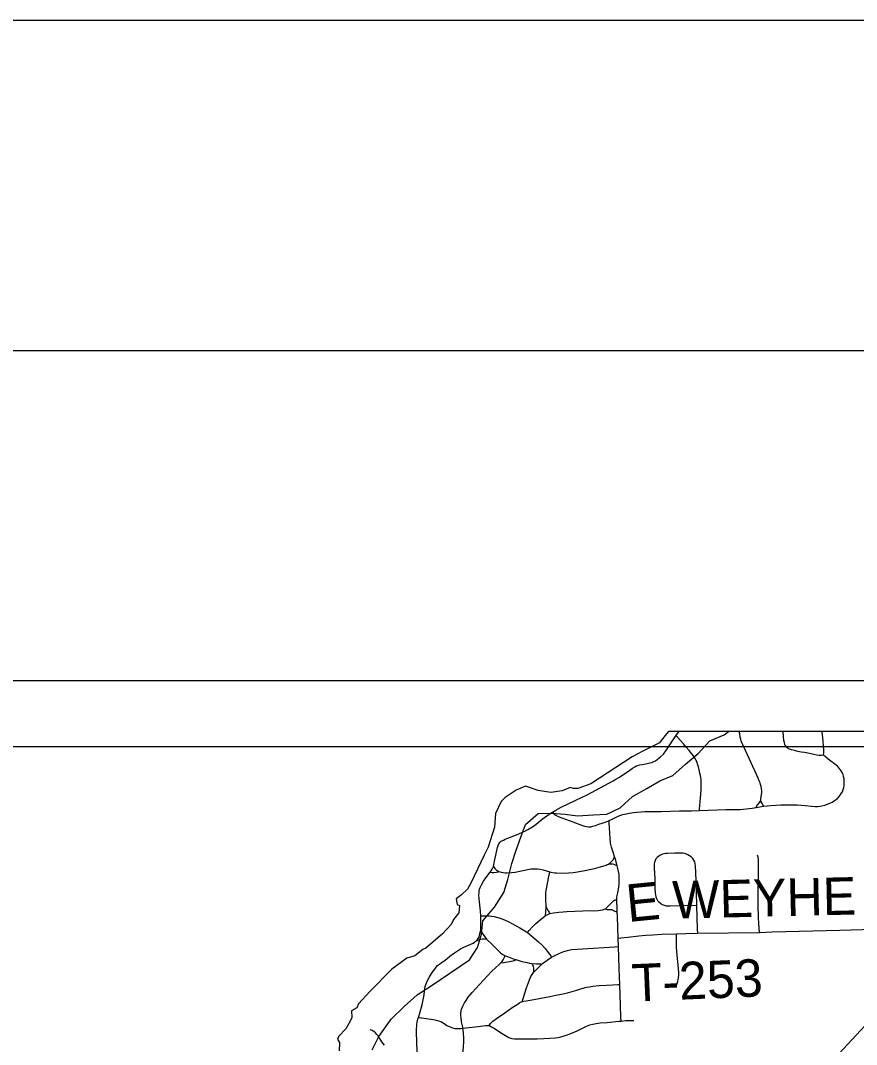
# Model space of a CAD drawing. Extents: x 63.4 to 97.4, y 0.4 to 22.4.
# Drawn here: x 67.147 to 68.414, y 20.868 to 22.42 of the extents above; entities that cross this region are included whole.
import ezdxf

# ---------------------------------------------------------------- set-up
doc = ezdxf.new("R2010")
doc.units = 0
for name, color, linetype in [('GM_X_County_Road', 7, 'Continuous'), ('GM_X_Major_Lake', 7, 'Continuous'), ('GM_X_Township_Road', 7, 'Continuous'), ('GM_X_Township_Road_Text', 7, 'Continuous'), ('SH_Border', 7, 'Continuous'), ('SH_Cut_Line', 7, 'Continuous'), ('SH_Data', 7, 'Continuous')]:
    doc.layers.add(name, color=color, linetype=linetype)

msp = doc.modelspace()

# ---------------------------------------------------------------- linework, layer by layer
at = {"layer": 'GM_X_County_Road'}
for points in [[(69.014, 21.3427), (68.1287, 21.3427), (68.1259, 21.3388), (68.1162, 21.3269), (68.1151, 21.3254), (68.0888, 21.312), (68.0738, 21.3043), (68.0114, 21.2632), (67.9915, 21.2561), (67.9849, 21.2559), (67.9798, 21.2576), (67.9678, 21.2528), (67.9506, 21.2499), (67.9313, 21.2531), (67.9121, 21.2599), (67.8979, 21.2536), (67.8814, 21.2424), (67.8754, 21.2367), (67.8665, 21.2183), (67.8653, 21.1977), (67.8557, 21.1674), (67.8494, 21.155), (67.8294, 21.1127), (67.8243, 21.1037), (67.8152, 21.095), (67.8072, 21.0889), (67.8087, 21.0803), (67.8123, 21.0787), (67.8113, 21.0677), (67.8029, 21.0578), (67.7996, 21.0501), (67.7865, 21.036), (67.761, 21.0143), (67.7564, 21.0123), (67.7444, 21.0026), (67.7325, 20.9991), (67.7094, 20.9826), (67.677, 20.9492), (67.6592, 20.9301), (67.6566, 20.924), (67.6487, 20.9191), (67.6488, 20.909), (67.6466, 20.9039), (67.6421, 20.8957), (67.6401, 20.8918), (67.6295, 20.8811), (67.6273, 20.8763), (67.6304, 20.8715), (67.6298, 20.8585)], [(68.3449, 20.8), (68.3483, 20.8062), (68.3529, 20.8134), (68.3582, 20.8212), (68.3639, 20.8286), (68.372, 20.8381), (68.3868, 20.8541), (68.4335, 20.9041), (68.4571, 20.9289), (68.5232, 20.999), (68.54, 21.0174), (68.546, 21.0244), (68.5516, 21.0318), (68.5584, 21.0421), (68.5614, 21.0469)]]:
    msp.add_lwpolyline(points, dxfattribs=at)
at = {"layer": 'GM_X_Major_Lake'}
for points in [[(67.9121, 21.2016), (67.9315, 21.2183), (67.9516, 21.2187), (67.9721, 21.2172), (67.991, 21.2149), (68.015, 21.216), (68.0354, 21.2172), (68.0556, 21.2271), (68.0745, 21.2438), (68.0958, 21.2559), (68.1159, 21.2677), (68.1356, 21.2757), (68.1546, 21.2932), (68.1736, 21.3091), (68.1914, 21.3285), (68.2134, 21.3376), (68.2196, 21.3427)], [(67.9121, 21.2016), (67.9315, 21.2183), (67.9516, 21.2187), (67.9721, 21.2172), (67.991, 21.2149), (68.015, 21.216), (68.0354, 21.2172), (68.0556, 21.2271), (68.0745, 21.2438), (68.0958, 21.2559), (68.1159, 21.2677), (68.1356, 21.2757), (68.1546, 21.2932), (68.1736, 21.3091), (68.1914, 21.3285), (68.2134, 21.3376), (68.2196, 21.3427)], [(67.6799, 20.8604), (67.6901, 20.8805), (67.7087, 20.9068), (67.7281, 20.9261), (67.7482, 20.9436), (67.7694, 20.9573), (67.8271, 20.9964), (67.8393, 21.0154), (67.8453, 21.0356), (67.8476, 21.0557), (67.8651, 21.0766), (67.8791, 21.0986), (67.8852, 21.1184), (67.8916, 21.1423), (67.8981, 21.1625), (67.9053, 21.1826), (67.9121, 21.2016)]]:
    msp.add_lwpolyline(points, dxfattribs=at)
at = {"layer": 'GM_X_Township_Road'}
for p, q in [((68.2619, 21.2275), (68.2735, 21.2295)), ((68.1731, 21.037), (68.2669, 21.0382)), ((68.0531, 21.0168), (68.0527, 21.0293))]:
    msp.add_line(p, q, dxfattribs=at)
for points in [[(67.9533, 21.2205), (67.9582, 21.2235), (67.9662, 21.2278), (67.9886, 21.2385), (68.0054, 21.2466), (68.0448, 21.2676), (68.0492, 21.2701), (68.0547, 21.2734), (68.0613, 21.2778), (68.068, 21.2824), (68.0743, 21.2869), (68.0778, 21.2891), (68.0798, 21.2903), (68.0822, 21.2912), (68.0851, 21.2919), (68.0889, 21.2926), (68.0947, 21.2933), (68.1008, 21.2948), (68.1037, 21.2957), (68.1066, 21.2969), (68.1093, 21.2983), (68.1119, 21.3), (68.1144, 21.3019), (68.1168, 21.3039), (68.1212, 21.3083), (68.125, 21.3131), (68.1301, 21.3209), (68.1401, 21.3361)], [(68.1401, 21.3361), (68.142, 21.3391), (68.145, 21.3427)], [(68.1756, 21.2226), (68.1759, 21.2261), (68.1761, 21.2295), (68.177, 21.2366), (68.1778, 21.2473), (68.1782, 21.2555), (68.1784, 21.2613), (68.1784, 21.2659), (68.1781, 21.2696), (68.1772, 21.2757), (68.1764, 21.2795), (68.1746, 21.2869), (68.1738, 21.2903), (68.173, 21.293), (68.1721, 21.2958), (68.1708, 21.2986), (68.1692, 21.3015), (68.1669, 21.3055), (68.1639, 21.3092), (68.1602, 21.3137), (68.1558, 21.319), (68.1518, 21.3237), (68.1418, 21.3343), (68.1401, 21.3361)], [(68.2685, 21.2385), (68.2688, 21.2407), (68.2695, 21.2441), (68.2703, 21.2495), (68.2703, 21.2526), (68.27, 21.2558), (68.2692, 21.2591), (68.2683, 21.2623), (68.2675, 21.2647), (68.2664, 21.2676), (68.2649, 21.2719), (68.2599, 21.283), (68.2453, 21.3138), (68.2414, 21.3225), (68.2394, 21.327), (68.2388, 21.3285), (68.2384, 21.3302), (68.2376, 21.3338), (68.2368, 21.3388), (68.2359, 21.3427)], [(68.3638, 21.3067), (68.3604, 21.3062), (68.3573, 21.3062), (68.3536, 21.3068), (68.3491, 21.3075), (68.3424, 21.309), (68.3349, 21.3105), (68.3298, 21.3113), (68.3249, 21.3124), (68.3196, 21.3135), (68.3153, 21.3146), (68.312, 21.3156), (68.3103, 21.3165), (68.3087, 21.3178), (68.3078, 21.3186), (68.3064, 21.3202), (68.3058, 21.3213), (68.3052, 21.323), (68.3044, 21.3257), (68.3037, 21.329), (68.303, 21.3347), (68.3024, 21.3427)], [(68.3638, 21.3067), (68.3642, 21.3107), (68.3641, 21.3141), (68.3625, 21.3336), (68.3615, 21.3412), (68.3614, 21.3427)], [(68.2735, 21.2295), (68.2834, 21.2306), (68.2989, 21.2315), (68.3112, 21.2315), (68.3238, 21.2312), (68.3359, 21.2303), (68.3454, 21.2295), (68.3512, 21.229), (68.3545, 21.2291), (68.358, 21.2294), (68.3613, 21.2298), (68.3656, 21.231), (68.3721, 21.2333), (68.3767, 21.2356), (68.3803, 21.2378), (68.3833, 21.2398), (68.3854, 21.2417), (68.3874, 21.2441), (68.3889, 21.2461), (68.3907, 21.2486), (68.3924, 21.2513), (68.3937, 21.2544), (68.3945, 21.2579), (68.3948, 21.2608), (68.395, 21.2641), (68.3949, 21.2671), (68.3948, 21.2707), (68.3942, 21.2745), (68.3934, 21.2775), (68.3922, 21.2802), (68.3903, 21.283), (68.3889, 21.2847), (68.3872, 21.287), (68.3852, 21.2893), (68.3806, 21.2933), (68.375, 21.2975), (68.3708, 21.3008), (68.3638, 21.3067)], [(68.1756, 21.2226), (68.2158, 21.2241), (68.2373, 21.2244), (68.2466, 21.2251), (68.2558, 21.2265), (68.2619, 21.2275)], [(68.2619, 21.2275), (68.2628, 21.2298), (68.2642, 21.2319), (68.2652, 21.2331), (68.2665, 21.2349), (68.2676, 21.2367), (68.2685, 21.2385)], [(68.2735, 21.2295), (68.2718, 21.2316), (68.2708, 21.2332), (68.2694, 21.2361), (68.2685, 21.2385)], [(67.8636, 21.1382), (67.8653, 21.1462), (67.8697, 21.1667), (67.8706, 21.1696), (67.8718, 21.1722), (67.8734, 21.1742), (67.8755, 21.1762), (67.8786, 21.1779), (67.8815, 21.1792), (67.8841, 21.1803), (67.8985, 21.1859), (67.9078, 21.1898), (67.9113, 21.1915), (67.9157, 21.1938), (67.9215, 21.1974), (67.9242, 21.1993), (67.9284, 21.2023), (67.9373, 21.2095), (67.9444, 21.2147), (67.9511, 21.2191), (67.9533, 21.2205)], [(67.9533, 21.2205), (67.9557, 21.2174), (67.9581, 21.2155), (67.9614, 21.2139), (67.9838, 21.2054), (67.9985, 21.2), (68.0017, 21.1989), (68.0046, 21.1984), (68.0076, 21.1981), (68.0109, 21.1983), (68.0142, 21.1989), (68.0183, 21.2002), (68.0232, 21.2019), (68.0282, 21.2037), (68.0342, 21.2058), (68.0389, 21.2075)], [(68.0389, 21.2075), (68.0426, 21.2094), (68.0453, 21.2108), (68.0483, 21.2124), (68.0514, 21.2137), (68.0549, 21.2151), (68.0595, 21.2166), (68.0647, 21.218), (68.0697, 21.219), (68.0756, 21.2198), (68.093, 21.2211), (68.1053, 21.2215), (68.1176, 21.2215), (68.1455, 21.2221), (68.1638, 21.2222), (68.1756, 21.2226)], [(68.0472, 21.1527), (68.0449, 21.1598), (68.0425, 21.1673), (68.0411, 21.1735), (68.0403, 21.1807), (68.0398, 21.1882), (68.0393, 21.1971), (68.0389, 21.2034), (68.0389, 21.2075)], [(68.0378, 21.1416), (68.0406, 21.1434), (68.0425, 21.1453), (68.0449, 21.148), (68.0461, 21.1502), (68.0472, 21.1527)], [(68.0509, 21.1389), (68.0503, 21.1411), (68.0478, 21.1507), (68.0472, 21.1527)], [(68.1718, 21.0794), (68.1706, 21.1172), (68.1698, 21.1389), (68.1694, 21.142), (68.1686, 21.145), (68.1673, 21.1477), (68.1655, 21.1502), (68.1633, 21.1524), (68.1608, 21.1543), (68.1581, 21.1558), (68.1552, 21.157), (68.1531, 21.1577), (68.1513, 21.1581), (68.1492, 21.1583), (68.1462, 21.1584), (68.1384, 21.1582), (68.1275, 21.1578), (68.1246, 21.1576), (68.1221, 21.1573), (68.1199, 21.1566), (68.1179, 21.1559), (68.1156, 21.1546), (68.1137, 21.1533), (68.1116, 21.1514), (68.1098, 21.1494), (68.1086, 21.1473), (68.1076, 21.1447), (68.1071, 21.1417), (68.1069, 21.1391), (68.107, 21.1355), (68.1079, 21.12), (68.1083, 21.1045), (68.1086, 21.0983), (68.109, 21.0953), (68.1097, 21.0922), (68.1108, 21.0893), (68.1124, 21.0866), (68.1143, 21.0842), (68.1166, 21.0822), (68.1192, 21.0805), (68.1221, 21.0793), (68.1251, 21.0786), (68.1282, 21.0783), (68.1313, 21.0783), (68.1718, 21.0794)], [(68.2669, 21.0382), (68.2658, 21.0517), (68.2653, 21.0609), (68.2646, 21.0795), (68.2645, 21.0888), (68.2646, 21.107), (68.2653, 21.1303), (68.2652, 21.1437), (68.265, 21.1485), (68.2646, 21.1519), (68.2637, 21.1552)], [(67.8586, 21.1294), (67.86, 21.1314), (67.8616, 21.1339), (67.8628, 21.1362), (67.8636, 21.1382)], [(67.8636, 21.1382), (67.8645, 21.1364), (67.8655, 21.1349), (67.8665, 21.1338), (67.8673, 21.1332), (67.8682, 21.1325), (67.8693, 21.1317), (67.8718, 21.1305)], [(67.8718, 21.1305), (67.8752, 21.1294), (67.8785, 21.129), (67.8814, 21.1285), (67.8845, 21.1282), (67.8908, 21.1287), (67.8967, 21.1294), (67.9178, 21.1341), (67.9208, 21.1345), (67.9238, 21.1346), (67.9301, 21.1344), (67.9342, 21.1338), (67.939, 21.133), (67.9489, 21.13)], [(67.9489, 21.13), (67.9504, 21.1296), (67.9563, 21.1285), (67.9593, 21.1283), (67.9683, 21.128), (67.9775, 21.1283), (67.9849, 21.1291), (67.9996, 21.1314), (68.0165, 21.1349), (68.0238, 21.1368), (68.0292, 21.1385), (68.0344, 21.1402), (68.0361, 21.1409), (68.0378, 21.1416)], [(68.0378, 21.1416), (68.0415, 21.142), (68.0444, 21.1419), (68.0472, 21.1411), (68.0492, 21.1401), (68.0509, 21.1389)], [(68.0505, 21.0876), (68.0506, 21.0908), (68.051, 21.0942), (68.0519, 21.0979), (68.0531, 21.1038), (68.0542, 21.1109), (68.0543, 21.1159), (68.0543, 21.1199), (68.054, 21.1253), (68.0535, 21.1286), (68.0525, 21.1329), (68.0509, 21.1389)], [(67.8443, 21.0633), (67.8438, 21.0705), (67.8419, 21.0891), (67.8416, 21.0952), (67.8417, 21.0983), (67.842, 21.1012), (67.8426, 21.1037), (67.8434, 21.1061), (67.8456, 21.1103), (67.8486, 21.1157), (67.8521, 21.1208), (67.8586, 21.1294)], [(67.8586, 21.1294), (67.8612, 21.1289), (67.8647, 21.129), (67.8681, 21.1294), (67.8702, 21.1297), (67.8711, 21.13), (67.8718, 21.1305)], [(67.9434, 21.0771), (67.9434, 21.0779), (67.9428, 21.0869), (67.9428, 21.0911), (67.9429, 21.0959), (67.943, 21.0988), (67.9434, 21.1017), (67.9477, 21.1229), (67.9485, 21.1275), (67.9489, 21.13)], [(68.0328, 21.0739), (68.0343, 21.0748), (68.0366, 21.0768), (68.0396, 21.08), (68.0454, 21.0858), (68.0465, 21.0867), (68.0481, 21.0873), (68.0505, 21.0876)], [(68.0511, 21.0698), (68.0509, 21.073), (68.0505, 21.0876)], [(67.9423, 21.0639), (67.9427, 21.065), (67.9432, 21.0686), (67.9434, 21.0771)], [(67.9434, 21.0771), (67.9446, 21.0741), (67.9461, 21.0714), (67.9478, 21.0686), (67.9487, 21.0675), (67.9492, 21.0666)], [(67.9492, 21.0666), (67.9547, 21.0678), (67.9626, 21.0688), (67.9693, 21.0692), (67.9747, 21.0696), (67.9869, 21.0704), (67.999, 21.0709), (68.0109, 21.0712), (68.0156, 21.071), (68.0224, 21.0713), (68.026, 21.0719), (68.0289, 21.0725), (68.0317, 21.0733), (68.0328, 21.0739)], [(68.0328, 21.0739), (68.0355, 21.073), (68.0385, 21.0729), (68.0411, 21.0728), (68.0426, 21.0727), (68.0439, 21.0724), (68.0456, 21.0715), (68.0477, 21.0704), (68.0488, 21.0699), (68.0499, 21.0698), (68.0511, 21.0698)], [(68.0527, 21.0293), (68.0515, 21.0622), (68.0511, 21.0698)], [(68.1731, 21.037), (68.173, 21.0426), (68.1718, 21.0794)], [(67.844, 21.0406), (67.8443, 21.0425), (67.8446, 21.0488), (67.8446, 21.0581), (67.8443, 21.0633)], [(67.8443, 21.0633), (67.8469, 21.0633), (67.8548, 21.0633), (67.8574, 21.0632), (67.8606, 21.0628), (67.8649, 21.062), (67.8704, 21.0607), (67.8751, 21.0592), (67.8811, 21.0568), (67.8869, 21.0542), (67.9035, 21.045), (67.9109, 21.0407), (67.9135, 21.0391), (67.9151, 21.0379)], [(67.9151, 21.0379), (67.9179, 21.041), (67.923, 21.0467), (67.9272, 21.0512), (67.9351, 21.0579), (67.9387, 21.0608), (67.9417, 21.0633), (67.9423, 21.0639)], [(67.9423, 21.0639), (67.946, 21.0653), (67.9492, 21.0666)], [(67.8372, 21.0252), (67.8395, 21.0276), (67.8404, 21.0289), (67.8414, 21.0305), (67.8423, 21.0333), (67.8432, 21.0363), (67.8438, 21.0394), (67.844, 21.0406)], [(67.844, 21.0406), (67.8507, 21.0313), (67.8531, 21.0279)], [(67.9151, 21.0379), (67.9184, 21.0353), (67.9319, 21.0237), (67.9377, 21.0183), (67.9419, 21.0136), (67.9449, 21.0098), (67.9486, 21.005), (67.9503, 21.0024), (67.9517, 21.0004)], [(68.2669, 21.0382), (68.286, 21.0389), (68.3885, 21.0417), (68.4568, 21.0435), (68.514, 21.0454)], [(67.7499, 20.9091), (67.7504, 20.9107), (67.7555, 20.9286), (67.7578, 20.9384), (67.7583, 20.9407), (67.7587, 20.9438), (67.7595, 20.9524), (67.7601, 20.9562), (67.761, 20.9592), (67.7637, 20.9652), (67.7661, 20.9698), (67.7709, 20.9773), (67.7746, 20.9826), (67.7768, 20.9855), (67.7789, 20.9879), (67.7817, 20.9902), (67.7849, 20.9924), (67.7899, 20.9957), (67.7976, 21.0022), (67.8028, 21.0061), (67.809, 21.0104), (67.8139, 21.0133), (67.8186, 21.0156), (67.8326, 21.022), (67.8351, 21.0235), (67.8372, 21.0252)], [(67.8372, 21.0252), (67.8413, 21.0268), (67.8442, 21.0277), (67.8471, 21.0283), (67.8497, 21.0283), (67.8531, 21.0279)], [(67.8531, 21.0279), (67.8609, 21.0202), (67.872, 21.0092), (67.8745, 21.0071), (67.8767, 21.0054), (67.8797, 21.0036), (67.8815, 21.0027)], [(68.0527, 21.0293), (68.0564, 21.0298), (68.0672, 21.0311)], [(68.0672, 21.0311), (68.084, 21.0329), (68.0946, 21.0338), (68.1053, 21.0345), (68.1189, 21.0353), (68.141, 21.0362)], [(68.1398, 20.955), (68.1429, 20.9639), (68.1441, 20.9696), (68.1443, 20.9733), (68.1443, 20.9772), (68.1441, 20.9828), (68.1416, 21.0094), (68.1411, 21.0162), (68.1408, 21.0224), (68.1408, 21.0313), (68.141, 21.0362)], [(68.141, 21.0362), (68.1551, 21.0365), (68.1731, 21.037)], [(67.9517, 21.0004), (67.9555, 21.0025), (67.965, 21.0071), (67.9702, 21.0092), (67.9757, 21.0109), (67.9821, 21.012), (67.9904, 21.0127), (67.9983, 21.0134), (68.0474, 21.0164), (68.0531, 21.0168)], [(68.0551, 20.9591), (68.0543, 20.9833), (68.0531, 21.0168)], [(67.8173, 20.893), (67.8171, 20.8947), (67.8153, 20.9028), (67.8145, 20.9091), (67.8142, 20.912), (67.8142, 20.916), (67.8147, 20.9193), (67.8154, 20.922), (67.8172, 20.9265), (67.8198, 20.9314), (67.822, 20.9348), (67.8255, 20.9399), (67.8315, 20.947), (67.8478, 20.9654), (67.8613, 20.9792), (67.8724, 20.9897), (67.8749, 20.9919)], [(67.8749, 20.9919), (67.8766, 20.9938), (67.8784, 20.9966), (67.8798, 20.9995), (67.8815, 21.0027)], [(67.8749, 20.9919), (67.8786, 20.9926), (67.8819, 20.9932), (67.888, 20.9942), (67.8929, 20.9951), (67.8952, 20.9957), (67.8974, 20.9969)], [(67.8815, 21.0027), (67.8822, 21.0024), (67.8948, 20.9978), (67.8974, 20.9969)], [(67.8974, 20.9969), (67.9064, 20.9942), (67.9147, 20.9923), (67.9183, 20.9916), (67.9214, 20.9911)], [(67.9214, 20.9911), (67.9286, 20.9906), (67.9331, 20.9907), (67.9342, 20.9907), (67.9352, 20.9906), (67.9367, 20.9899)], [(67.9214, 20.9911), (67.9226, 20.9896), (67.9233, 20.9882), (67.9239, 20.9863), (67.9241, 20.9844), (67.9242, 20.9828), (67.9242, 20.9808), (67.9241, 20.9774)], [(67.9367, 20.9899), (67.9378, 20.991), (67.9412, 20.9934), (67.9451, 20.9962), (67.9517, 21.0004)], [(67.9077, 20.9335), (67.9082, 20.9366), (67.909, 20.9396), (67.9139, 20.9542), (67.9183, 20.9664), (67.9202, 20.9711), (67.922, 20.9745), (67.9241, 20.9774)], [(67.9241, 20.9774), (67.9278, 20.9811), (67.9322, 20.9857), (67.9367, 20.9899)], [(67.9077, 20.9335), (67.9094, 20.9339), (67.913, 20.9347), (67.919, 20.9355), (67.9246, 20.9364), (67.9492, 20.941), (67.9583, 20.9429), (67.9669, 20.9445), (67.9757, 20.9466), (67.9898, 20.9504), (67.9947, 20.9519), (68.0024, 20.9547), (68.0048, 20.9553), (68.009, 20.9559), (68.0142, 20.9565), (68.0236, 20.9577), (68.0348, 20.9582), (68.0445, 20.9589), (68.0523, 20.959), (68.0551, 20.9591)], [(68.0571, 20.9039), (68.0568, 20.9102), (68.0556, 20.9433), (68.0551, 20.9591)], [(67.8572, 20.8969), (67.8581, 20.8985), (67.8589, 20.8999), (67.8599, 20.9012), (67.8628, 20.9038), (67.8682, 20.9075), (67.8808, 20.9164), (67.8917, 20.9242), (67.8995, 20.929), (67.9037, 20.9318), (67.9069, 20.9332), (67.9077, 20.9335)], [(67.7494, 20.8231), (67.7484, 20.8487), (67.7474, 20.8704), (67.7472, 20.8892), (67.7475, 20.8989), (67.748, 20.9022), (67.7484, 20.9045), (67.7492, 20.907), (67.7499, 20.9091)], [(67.7499, 20.9091), (67.7533, 20.9089), (67.7549, 20.9088), (67.7616, 20.9079), (67.7726, 20.906), (67.7768, 20.9052), (67.7804, 20.9042), (67.7841, 20.9029), (67.7866, 20.9016), (67.7891, 20.8999), (67.7931, 20.8973), (67.7988, 20.8946), (67.8015, 20.8934), (67.8053, 20.8925), (67.8089, 20.8924), (67.8142, 20.8925), (67.8173, 20.893)], [(67.8572, 20.8969), (67.858, 20.8966), (67.8608, 20.895), (67.8645, 20.8928), (67.8759, 20.8854), (67.8817, 20.8819), (67.8869, 20.8789), (67.8914, 20.8773), (67.8953, 20.877), (67.8994, 20.8767), (67.9116, 20.8767), (67.9299, 20.8771), (67.9397, 20.8776), (67.9492, 20.878), (67.9572, 20.8785), (67.9616, 20.8791), (67.9659, 20.8798), (67.9693, 20.8808), (67.9767, 20.8834), (67.9834, 20.8861), (67.9902, 20.8891), (67.9963, 20.892), (68.0005, 20.8941), (68.0047, 20.8963), (68.0095, 20.8982), (68.0141, 20.8992), (68.0192, 20.9001), (68.0255, 20.9009), (68.0361, 20.9017), (68.0538, 20.9037), (68.0571, 20.9039)], [(68.0571, 20.9039), (68.0636, 20.9045), (68.0764, 20.9047)], [(67.6984, 20.8675), (67.6946, 20.8724), (67.6887, 20.8815), (67.6868, 20.8837), (67.6848, 20.8858), (67.6824, 20.8878), (67.6799, 20.8893), (67.677, 20.8905)], [(67.8144, 20.8214), (67.815, 20.8235), (67.8155, 20.8265), (67.816, 20.833), (67.8169, 20.8457), (67.8184, 20.8653), (67.8188, 20.8722), (67.8188, 20.877), (67.818, 20.8864), (67.8173, 20.893)], [(67.8173, 20.893), (67.8406, 20.8954), (67.8514, 20.897), (67.8538, 20.8973), (67.8559, 20.8973), (67.8572, 20.8969)]]:
    msp.add_lwpolyline(points, dxfattribs=at)
at = {"layer": 'SH_Border'}
msp.add_lwpolyline([(64.9123, 21.9197), (96.9123, 21.9197), (96.9123, 0.9197), (64.9123, 0.9197)], close=True, dxfattribs=at)
at = {"layer": 'SH_Cut_Line'}
msp.add_lwpolyline([(63.4123, 0.4197), (97.4123, 0.4197), (97.4123, 22.4197), (63.4123, 22.4197)], close=True, dxfattribs=at)
msp.add_lwpolyline([(69.014, 21.3427), (68.1287, 21.3427), (68.1259, 21.3388), (68.1162, 21.3269), (68.1151, 21.3254), (68.0888, 21.312), (68.0738, 21.3043), (68.0114, 21.2632), (67.9915, 21.2561), (67.9849, 21.2559), (67.9798, 21.2576), (67.9678, 21.2528), (67.9506, 21.2499), (67.9313, 21.2531), (67.9121, 21.2599), (67.8979, 21.2536), (67.8814, 21.2424), (67.8754, 21.2367), (67.8665, 21.2183), (67.8653, 21.1977), (67.8557, 21.1674), (67.8494, 21.155), (67.8294, 21.1127), (67.8243, 21.1037), (67.8152, 21.095), (67.8072, 21.0889), (67.8087, 21.0803), (67.8123, 21.0787), (67.8113, 21.0677), (67.8029, 21.0578), (67.7996, 21.0501), (67.7865, 21.036), (67.761, 21.0143), (67.7564, 21.0123), (67.7444, 21.0026), (67.7325, 20.9991), (67.7094, 20.9826), (67.677, 20.9492), (67.6592, 20.9301), (67.6566, 20.924), (67.6487, 20.9191), (67.6488, 20.909), (67.6466, 20.9039), (67.6421, 20.8957), (67.6401, 20.8918), (67.6295, 20.8811), (67.6273, 20.8763), (67.6304, 20.8715), (67.6298, 20.8585)], dxfattribs=at)
at = {"layer": 'SH_Data'}
for p, q in [((65.4123, 21.4197), (72.4123, 21.4197)), ((65.5123, 21.3197), (72.3123, 21.3197))]:
    msp.add_line(p, q, dxfattribs=at)

# ---------------------------------------------------------------- texts
at = {"layer": 'GM_X_Township_Road_Text'}
for s, height, rotation, p in [('WEYHE', 0.05682, 1.3142, (68.1352, 21.0589)), ('E', 0.0568, 5.584, (68.0676, 21.0538)), ('T-253', 0.05682, 2.4084, (68.0742, 20.9331))]:
    msp.add_text(s, height=height, rotation=rotation, dxfattribs=at).set_placement(p)

doc.saveas('drawing.dxf')
